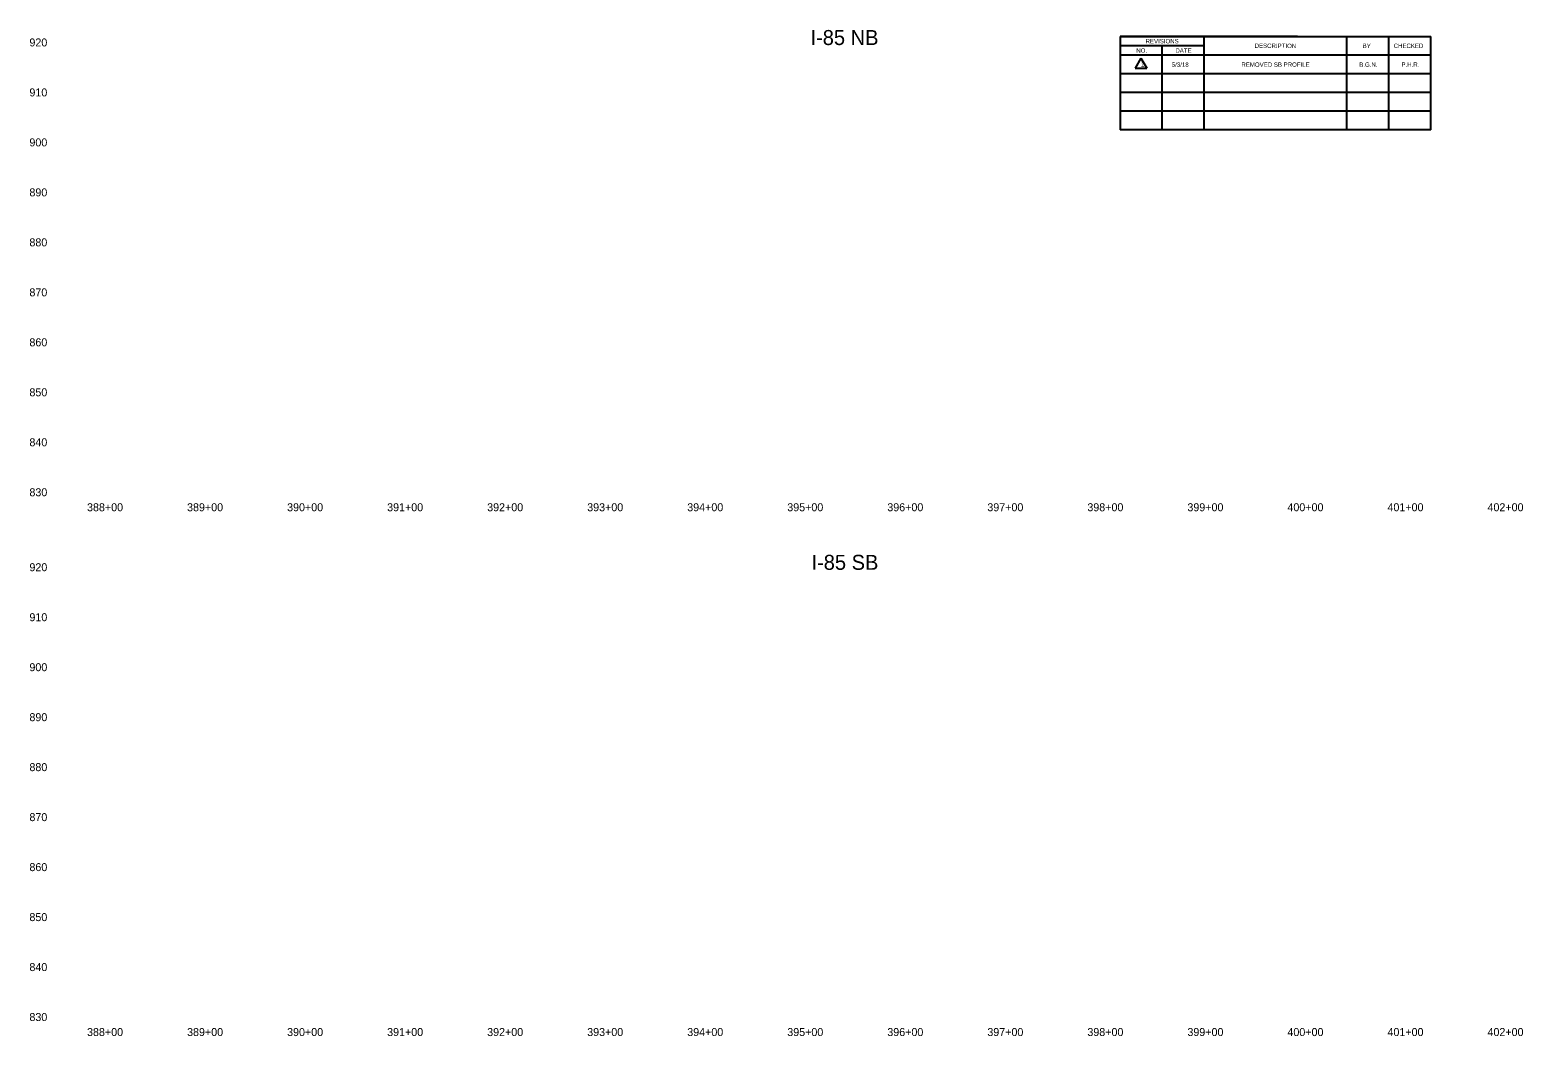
# Model space of a CAD drawing. Extents: x 16991142 to 16994107, y 12627821 to 12628870.
# Drawn here: x 16991142 to 16992634, y 12627821 to 12628828 of the extents above; entities that cross this region are included whole.
import ezdxf

# ---------------------------------------------------------------- set-up
doc = ezdxf.new("R2010")
doc.units = 0
doc.layers.add('Default', color=7, linetype='Continuous')
doc.layers.add('RD_SHT_TX', color=7, linetype='Continuous')

msp = doc.modelspace()

# ---------------------------------------------------------------- linework, layer by layer
at = {"layer": 'RD_SHT_TX'}
for p, q in [((16992231.7, 12628821.5), (16992542.3, 12628821.5)), ((16992408.9, 12628821.5), (16992231.7, 12628821.5)), ((16992231.7, 12628821.5), (16992231.7, 12628728)), ((16992315.7, 12628728), (16992315.7, 12628821.5)), ((16992458.3, 12628728), (16992458.3, 12628821.5)), ((16992500.3, 12628728), (16992500.3, 12628821.5)), ((16992542.3, 12628728), (16992542.3, 12628821.5)), ((16992315.7, 12628812.2), (16992231.7, 12628812.2)), ((16992542.3, 12628802.8), (16992231.7, 12628802.8)), ((16992273.7, 12628728), (16992273.7, 12628812.2)), ((16992252.4, 12628799.9), (16992246.7, 12628789.7)), ((16992246.7, 12628789.7), (16992258.1, 12628789.7)), ((16992252.4, 12628799.9), (16992258.1, 12628789.7)), ((16992542.3, 12628784.1), (16992231.7, 12628784.1)), ((16992542.3, 12628765.4), (16992231.7, 12628765.4)), ((16992542.3, 12628746.7), (16992231.7, 12628746.7)), ((16992542.3, 12628728), (16992231.7, 12628728))]:
    msp.add_line(p, q, dxfattribs=at)

# ---------------------------------------------------------------- texts
at = {"layer": 'Default'}
for s, p in [('920', (16991141.2, 12628811.6)), ('910', (16991141.2, 12628761.6)), ('900', (16991141.2, 12628711.6)), ('890', (16991141.2, 12628661.6)), ('880', (16991141.2, 12628611.6)), ('870', (16991141.2, 12628561.6)), ('860', (16991141.2, 12628511.6)), ('850', (16991141.2, 12628461.6)), ('840', (16991141.2, 12628411.6)), ('830', (16991141.2, 12628361.6)), ('388+00', (16991198.8, 12628346.6)), ('389+00', (16991298.8, 12628346.6)), ('390+00', (16991398.8, 12628346.6)), ('391+00', (16991498.8, 12628346.6)), ('392+00', (16991598.8, 12628346.6)), ('393+00', (16991698.8, 12628346.6)), ('394+00', (16991798.8, 12628346.6)), ('395+00', (16991898.8, 12628346.6)), ('396+00', (16991998.8, 12628346.6)), ('397+00', (16992098.8, 12628346.6)), ('398+00', (16992198.8, 12628346.6)), ('399+00', (16992298.8, 12628346.6)), ('400+00', (16992398.8, 12628346.6)), ('401+00', (16992498.8, 12628346.6)), ('402+00', (16992598.8, 12628346.6)), ('920', (16991141.2, 12628286.6)), ('910', (16991141.2, 12628236.6)), ('900', (16991141.2, 12628186.6)), ('890', (16991141.2, 12628136.6)), ('880', (16991141.2, 12628086.6)), ('870', (16991141.2, 12628036.6)), ('860', (16991141.2, 12627986.6)), ('850', (16991141.2, 12627936.6)), ('840', (16991141.2, 12627886.6)), ('830', (16991141.2, 12627836.6)), ('388+00', (16991198.8, 12627821.6)), ('389+00', (16991298.8, 12627821.6)), ('390+00', (16991398.8, 12627821.6)), ('391+00', (16991498.8, 12627821.6)), ('392+00', (16991598.8, 12627821.6)), ('393+00', (16991698.8, 12627821.6)), ('394+00', (16991798.8, 12627821.6)), ('395+00', (16991898.8, 12627821.6)), ('396+00', (16991998.8, 12627821.6)), ('397+00', (16992098.8, 12627821.6)), ('398+00', (16992198.8, 12627821.6)), ('399+00', (16992298.8, 12627821.6)), ('400+00', (16992398.8, 12627821.6)), ('401+00', (16992498.8, 12627821.6)), ('402+00', (16992598.8, 12627821.6))]:
    msp.add_text(s, height=8, dxfattribs=at).set_placement(p)
at = {"layer": 'RD_SHT_TX'}
for s, height, p in [('I-85 NB', 15, (16991922, 12628813)), ('REVISIONS', 4.4, (16992257, 12628814.7)), ('NO.', 4.4, (16992247.7, 12628805.3)), ('CHECKED', 4.4, (16992505, 12628810)), ('1', 4.4, (16992252.4, 12628791.4)), ('5/3/18', 4.4, (16992283.2, 12628791.2)), ('REMOVED SB PROFILE', 4.4, (16992352.8, 12628791.2)), ('B.G.N.', 4.4, (16992470.6, 12628791.2)), ('P.H.R.', 4.4, (16992512.8, 12628791.2)), ('I-85 SB', 15, (16991923, 12628288))]:
    msp.add_text(s, height=height, dxfattribs=at).set_placement(p)
for s, height, p in [('DATE', 4.41, (16992286.8, 12628805.3)), ('DESCRIPTION', 4.408, (16992366, 12628810.1)), ('BY', 4.41, (16992474, 12628810))]:
    msp.add_text(s, height=height, rotation=359.7246, dxfattribs=at).set_placement(p)

doc.saveas('drawing.dxf')
